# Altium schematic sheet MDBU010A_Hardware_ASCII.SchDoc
size 431 x 279 mm; Date: Not shown in title block; ApprovedBy: Not shown in title block; CheckedBy: Not shown in title block; Author: Not shown in title block; CompanyName: Not shown in title block; Engineer: Not shown in title block; Organization: Not shown in title block; Address1: Not shown in title block; Address2: Not shown in title block; Address3: Not shown in title block; Address4: Not shown in title block; DocumentNumber: 1; Revision: Use project parameter SCH_Rev; SheetNumber: 2; SheetTotal: 2; PageSetup: Record=PageOptions¦CenterHorizontal=True¦CenterVertical=True¦PrintScale=1.00¦XCorrection=1.00¦YCorrection=1.00¦PrintKind=0¦BorderSize=5000000¦LeftOffset=0¦BottomOffset=0¦Orientation=2¦PaperLength=1000¦PaperWidth=1000¦Scale=100¦PaperSource=15¦PrintQuality=600¦MediaType=1¦DitherType=10¦PaperKind=Letter¦PrintScaleMode=1
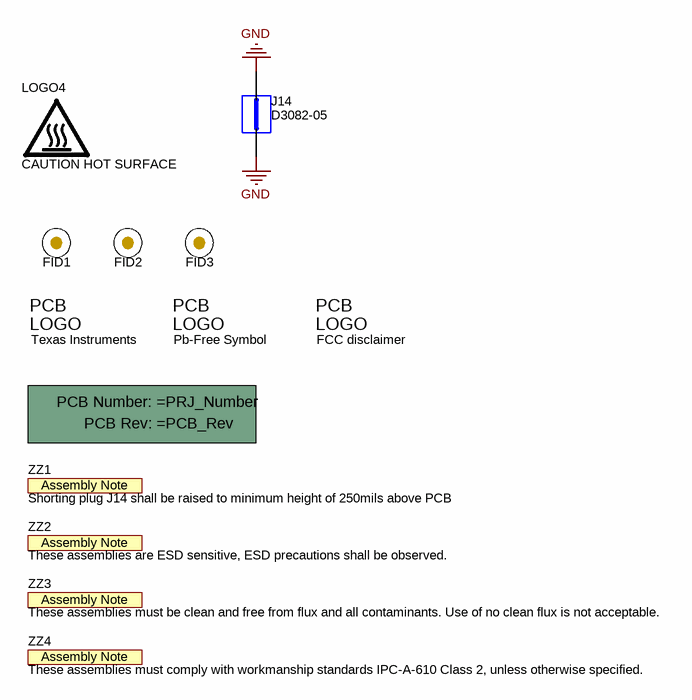
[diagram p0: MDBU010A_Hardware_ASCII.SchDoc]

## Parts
!PCB  Printed Circuit Board  (value not drawn)  (mechanical)
FID1  Fiducial  [Fiducial10-20]  (value not drawn)
FID2  Fiducial  [Fiducial10-20]  (value not drawn)
FID3  Fiducial  [Fiducial10-20]  (value not drawn)
J14  D3082-05  [Harwin_D3082-05]
Logo1  Texas Instruments  [TI_Stacked_Overlay_Small]  (no BOM)
Logo2  Pb-Free Symbol  [Pb-Free_Overlay_Medium]  (no BOM)
Logo3  FCC disclaimer  [FCC_disclaimer]  (no BOM)
LOGO4  CAUTION HOT SURFACE  [IEC_HotSurface_Small]  (no BOM)
ZZ1  Shorting plug J14 shall be raised to minimum height of 250mils above PCB  [AssemblyNote]  (no BOM)
ZZ2  These assemblies are ESD sensitive, ESD precautions shall be observed.  [AssemblyNote]  (no BOM)
ZZ3  These assemblies must be clean and free from flux and all contaminants. Use of no clean flux is not acceptable.  [AssemblyNote]  (no BOM)
ZZ4  These assemblies must comply with workmanship standards IPC-A-610 Class 2, unless otherwise specified.  [AssemblyNote]  (no BOM)

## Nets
GND: J14.1 J14.2

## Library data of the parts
!PCB = PCB: Manufacturer: Any; SymbolCreator: a0412235
FID1-FID3 = Fiducial: Fiducial mark.  There is nothing to buy or mount.; SymbolCreator: codlsc
J14 = D3082-05: 1mm Uninsulated Shorting Plug, 10.16mm spacing, TH; Manufacturer: Harwin; SymbolCreator: a0799628; CompType: Jumper Wire; U/M: EA
Logo1 = TI_Logo: Texas Instrument Corporate Signature; SymbolCreator: codlsc
Logo2 = Pb-Free: SymbolCreator: a0412235
Logo3 = FCC_disclaimer: SymbolCreator: codlsc
LOGO4 = IEC_HotSurface: IEC 61010-1 Hot Surface Warning; SymbolCreator: a0412235
ZZ1-ZZ4 = AssemblyNote: SymbolCreator: codlsc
